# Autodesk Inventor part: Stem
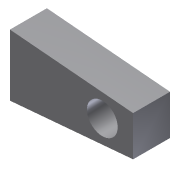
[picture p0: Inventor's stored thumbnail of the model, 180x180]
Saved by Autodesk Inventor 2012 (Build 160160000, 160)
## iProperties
Created: 2012-02
Part Number: Stem
Material: Default
Document SubType Name: Modeling
Designer: cadcim
Density: 1 g/cm^3
Author: cadcim
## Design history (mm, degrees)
sketch "Sketch1"
  geometry: 1 further point
sketch "Sketch2"
  geometry: L1 (20, -3)-(20, 3); L2 (20, 3)-(0, 3); L3 (0, 3)-(0, -3); L4 (20, -3)-(0, -3); 2 further points
  constraints: 8 end point, 2 perpendicular, 1 coincident, 1 horizontal, 1 midpoint, 1 parallel
  dimensions: "d9" = 20 distance of L1.end L2.end; "d10" = 6 distance of L1.start L1.end
extrude "Extrusion1" new body sketch "Sketch2" stored distance "d2" = 10; taper "d3" = 0 deg
hole "Hole1" diameter "d13" = 5; stored, may be unused: countersink angle "d17" = 90 deg, drill point angle "d19" = 118 deg; dims "d11" = 5, "d12" = 5, "d14" = 6, "d15" = 4, "d16" = 2, "d18" = 8
sketch "Sketch4"
  geometry: L1 (0, 0)-(20, -1.75); L2 (0, 0)-(20.076, 0); L3 (0, -10)-(20, -8.25); L4 (20, -1.75)-(20, 0); L5 (0, 0)-(20, 0); L6 (20, -8.25)-(20, -10); L7 (20, -10)-(0, -10)
  constraints: 14 end point, 4 perpendicular, 1 equal length, 1 horizontal, 1 point on line
  dimensions: "d20" = 5 deg angle of L1 L2
extrude "Extrusion3" cut sketch "Sketch4" distance "d21" = 21.25; taper "d22" = 0 deg
body "Solid1"
